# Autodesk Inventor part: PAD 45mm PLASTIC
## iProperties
Created: 2007-03
Part Number: PAD 45mm PLASTIC
Document SubType Name: Modeling
Designer: Andy Moles
Material: ABS Plastic
Mass: 16.1926 g
Surface Area: 57.8063 cm^2
Volume: 15.276 cm^3
Density: 1.06 g/cm^3
Author: Andy Moles
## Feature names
1. Revolution1
2. Extrusion1
3. Extrusion2
